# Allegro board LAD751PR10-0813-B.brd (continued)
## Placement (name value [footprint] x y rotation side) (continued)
PC512  0.022U_0402_25V7K  [C_0402]  133.09 140.24 180 bottom
PC513  0.01UF_0402_25V7K  [C_0402]  122.93 141.45 0 top
PC514  1500P_0402_50V7K  [C_0402]  134.03 143.89 270 bottom
PC515  0.01UF_0402_25V7K  [C_0402]  129.74 138.46 180 top
PC516  0.15U_0402_16V7K  [C_0402]  120.39 140.76 180 bottom
PC517  0.033U_0402_16V7K  [C_0402]  120.39 141.65 180 bottom
PC518  2200P_0402_50V7K  [C_0402]  121.39 143.63 270 bottom
PC519  330P_0402_50V7K  [C_0402]  129.68 143.21 90 top
PC520  68P_0402_50V8J  [C_0402]  127.89 142.34 0 top
PC521  2200P_0402_50V7K  [C_0402]  129.74 140.3 180 top
PC522  680P_0402_50V7K  [C_0402]  133.09 145.65 180 bottom
PC523  .1U_0402_16V7K  [C_0402]  120.49 145.4 0 bottom
PC524  0.022U_0402_25V7K  [C_0402]  130.03 146.02 90 bottom
PC525  0.022U_0402_25V7K  [C_0402]  120.68 142.99 0 top
PC526  0.022U_0402_25V7K  [C_0402]  128.19 145.96 90 top
PC527  0.022U_0402_25V7K  [C_0402]  127.3 145.96 90 top
PC528  0.022U_0402_25V7K  [C_0402]  120.68 142.1 0 top
PC529  .1U_0402_16V7K  [C_0402]  129.98 147.86 0 bottom
PC530  4700P_0402_16V7K  [C_0402]  125.27 146.94 270 top
PC531  0.22U_0402_16V7K  [C_0402]  126.15 146.94 270 top
PC532  2200P_0402_50V7K  [C_0402]  127.29 146.92 0 bottom
PC533  470P_0402_50V7K  [C_0402]  126.17 147.81 180 bottom
PC534  0.01UF_0402_25V7K  [C_0402]  127.13 144.64 270 top
PC535  330P_0402_50V7K  [C_0402]  123.87 142.85 90 top
PC536  68P_0402_50V8J  [C_0402]  125.04 142.54 270 top
PC537  680P_0402_50V7K  [C_0402]  123.5 147.81 180 bottom
PC538  6800P_0402_25V7K  [C_0402]  125.93 141.63 90 top
PC539  100U_25V_M  [C_ECST250ADA101MF611]  144.66 155 270 bottom
PC540  1U_0402_6.3V6K  [C_0402]  158.11 144.99 90 top
PC541  0.22U_0603_16V7K  [C_0603]  160.42 147.71 270 bottom
PC542  100U_25V_M  [C_ECST250ADA101MF611]  151.77 154.94 270 bottom
PC543  10U_0805_25V6K  [C_0805]  160.17 143.26 270 top
PC544  10U_0805_25V6K  [C_0805]  161.89 143.26 270 top
PC545  10U_0805_25V6K  [C_0805]  160.44 144.39 90 top
PC546  0.1U_0402_25V6  [C_0402]  163.19 141.8 0 top
PC547  2200P_0402_50V7K  [C_0402]  159.14 144.27 90 top
PC548  33P_0603_50V8J  [C_0603]  161.23 136.24 0 top
PC549  1U_0402_6.3V6K  [C_0402]  169.46 147.24 180 top
PC550  0.22U_0603_16V7K  [C_0603]  168.75 147.63 270 bottom
PC551  10U_0805_25V6K  [C_0805]  168.59 143.21 270 top
PC552  10U_0805_25V6K  [C_0805]  170.32 143.21 270 top
PC553  10U_0805_25V6K  [C_0805]  170.08 144.38 90 top
PC554  0.1U_0402_25V6  [C_0402]  171.4 144.22 90 top
PC555  2200P_0402_50V7K  [C_0402]  168.73 144.56 90 top
PC556  33P_0603_50V8J  [C_0603]  169.87 136.24 0 top
PC557  1U_0402_6.3V6K  [C_0402]  174.88 144.74 90 top
PC558  0.22U_0603_16V7K  [C_0603]  177.1 147.69 270 bottom
PC559  10U_0805_25V6K  [C_0805]  177.3 144.41 90 top
PC560  10U_0805_25V6K  [C_0805]  178.6 143.23 270 top
PC561  10U_0805_25V6K  [C_0805]  176.84 143.23 270 top
PC562  0.1U_0402_25V6  [C_0402]  178.65 144.25 90 top
PC563  2200P_0402_50V7K  [C_0402]  179.54 144.25 90 top
PC564  33P_0603_50V8J  [C_0603]  178.12 136.24 0 top
PC565  10U_0805_25V6K~D  [C_0805]  145.3 147.91 180 top
PC566  1U_0402_6.3V6K  [C_0402]  142.25 147.98 90 top
PC567  0.22U_0603_16V7K  [C_0603]  144.41 150.95 270 bottom
PC568  10U_0805_25V6K~D  [C_0805]  143.96 146.5 270 top
PC569  10U_0805_25V6K~D  [C_0805]  145.7 146.5 270 top
PC570  680P_0603_50V7K  [C_0603]  145.29 139.42 0 top
PC571  0.1U_0402_25V6  [C_0402]  147.15 147.49 90 top
PC572  2200P_0402_50V7K  [C_0402]  146.29 147.49 90 top
PC573  1U_0402_6.3V6K  [C_0402]  150.56 147.98 90 top
PC574  0.22U_0603_16V7K  [C_0603]  152.74 150.98 270 bottom
PC575  10U_0805_25V6K~D  [C_0805]  152.54 146.52 270 top
PC576  10U_0805_25V6K~D  [C_0805]  154.29 146.52 270 top
PC577  10U_0805_25V6K~D  [C_0805]  153.83 147.96 180 top
PC578  0.1U_0402_25V6  [C_0402]  154.83 147.52 90 top
PC579  2200P_0402_50V7K  [C_0402]  155.7 147.69 90 top
PC580  680P_0603_50V7K  [C_0603]  153.87 139.42 0 top
PC581  2200P_0402_50V7K  [C_0402]  186.89 139.4 270 top
PC582  0.1U_0402_25V6  [C_0402]  187.77 139.39 270 top
PC583  10U_0805_25V6K  [C_0805]  182.99 139.19 270 top
PC584  10U_0805_25V6K  [C_0805]  184.7 139.19 270 top
PC585  10U_0805_25V6K  [C_0805]  184.82 143.61 180 top
PC586  0.22U_0603_16V7K  [C_0603]  183.94 146.16 270 bottom
PC587  680P_0603_50V7K  [C_0603]  183.65 134.91 270 top
PC588  4.7U_0402_6.3V6M  [C_0402]  183.92 145.38 180 top
PC589  2200P_0402_50V7K  [C_0402]  118.64 117.38 180 bottom
PC590  0.22U_0402_10V6K  [C_0402]  124.58 117.7 0 bottom
PC591  680P_0603_50V7K  [C_0603]  118.44 108.11 270 bottom
PC592  10U_0805_25V6K  [C_0805]  120 119.73 0 bottom
PC593  0.1U_0603_25V7K  [C_0603]  119.45 113.13 0 bottom
PC594  0.1U_0402_25V6  [C_0402]  118.64 116.49 180 bottom
PC596  22U_0603_6.3V6M  [C_0603]  122.62 103.86 180 bottom
PC597  22U_0603_6.3V6M  [C_0603]  122.62 105.19 180 bottom
PC598  22U_0603_6.3V6M  [C_0603]  124.78 105.19 0 bottom
PC599  22U_0603_6.3V6M  [C_0603]  124.78 103.86 0 bottom
PC701  0.1U_0402_25V6  [C_0402]  58.05 28.67 180 top
PC702  0.047U_0402_25V7K  [C_0402]  61.78 23.21 0 top
PC703  0.1U_0402_25V6  [C_0402]  64.33 27.21 270 top
PC704  2200P_0402_50V7K  [C_0402]  63.45 27.21 270 top
PC705  10U_0805_25V6K~D  [C_0805]  65.73 27.08 270 top
PC706  10U_0805_25V6K~D  [C_0805]  67.51 27.08 270 top
PC707  0.1U_0603_25V7K  [C_0603]  58.37 22.61 90 bottom
PC708  0.1U_0402_25V6  [C_0402]  58.48 25.75 0 bottom
PC709  0.01UF_0402_25V7K  [C_0402]  59.64 24.56 270 bottom
PC710  2.2U_0603_16V6K  [C_0603]  59.23 21.37 180 bottom
PC711  1U_0603_25V6K  [C_0603]  59.44 22.64 0 bottom
PC712  22U_0805_25V6M  [C_0805]  82.47 26.91 90 bottom
PC713  22U_0805_25V6M  [C_0805]  84.18 26.91 90 bottom
PC714  22U_0805_25V6M  [C_0805]  86.03 26.94 90 bottom
PC715  680P_0402_50V7K  [C_0402]  63.76 21.04 90 top
PC716  0.1U_0402_25V6  [C_0402]  57.4 15.91 0 top
PC717  0.1U_0402_25V6  [C_0402]  58.31 16.8 180 top
PC718  100P_0402_50V8J  [C_0402]  52.96 24.69 0 top
PC719  0.01UF_0402_25V7K  [C_0402]  56.34 24.86 270 bottom
PC720  100P_0402_50V8J  [C_0402]  52.97 23.8 0 top
PC721  0.1U_0402_25V6  [C_0402]  56.52 16.81 270 top
PC722  1000P_0402_50V7K  [C_0402]  70.11 40.56 180 top
PC723  1000P_0402_50V7K  [C_0402]  69.92 33.37 180 top
PC724  0.1U_0402_25V6  [C_0402]  118.65 78.77 180 top
PC725  0.022U_0603_25V7K  [C_0603]  79.93 28.34 90 top
PC726  1000P_0402_50V7K  [C_0402]  62.56 27.22 270 top
PC727  1U_0402_25V6K  [C_0402]  61.67 27.22 270 top
PC800  10U_0805_25V6K~D  [C_0805]  245.12 38.77 90 bottom
PC801  0.1U_0402_16V7K  [C_0402]  238.08 39.85 180 bottom
PC802  680P_0402_50V7K  [C_0402]  247.8 45.31 0 bottom
PC803  2.2U_0402_16V6K  [C_0402]  241.31 42.78 270 top
PC804  22U_0603_6.3V6M  [C_0603]  240.42 46.58 90 bottom
PC805  22U_0603_6.3V6M  [C_0603]  239.15 46.58 90 bottom
PC806  680P_0402_50V7K  [C_0402]  234.44 44.04 0 bottom
PC807  2.2U_0402_16V6K  [C_0402]  122.61 113.44 0 bottom
PC808  0.1U_0603_25V7K  [C_0603]  248.62 42.95 180 bottom
PC809  330P_0402_50V7K  [C_0402]  237.17 43.4 0 bottom
PC810  10U_0805_25V6K~D  [C_0805]  229.93 35.4 0 bottom
PC811  0.1U_0402_16V7K  [C_0402]  226.07 38.56 90 bottom
PC812  22U_0603_6.3V6M  [C_0603]  224.86 44.81 270 bottom
PC813  22U_0603_6.3V6M  [C_0603]  223.59 44.81 270 bottom
PC814  10U_0805_25V6K~D  [C_0805]  229.85 37.12 0 bottom
PC815  22U_0603_6.3V6M  [C_0603]  236.67 46.58 90 bottom
PC816  22U_0603_6.3V6M  [C_0603]  237.94 46.58 90 bottom
PC817  1U_0603_6.3V6M  [C_0603]  239.14 44.3 0 bottom
PC818  330P_0402_50V7K  [C_0402]  122.13 122.84 180 bottom
PC819  330P_0402_50V7K  [C_0402]  222.45 42.53 270 bottom
PC820  22U_0603_6.3V6M  [C_0603]  224.86 45.78 90 bottom
PC821  1U_0603_6.3V6M  [C_0603]  226.13 42.32 180 bottom
PC822  2.2U_0402_16V6K  [C_0402]  229.56 43.4 180 bottom
PC823  0.1U_0603_25V7K  [C_0603]  234.07 42.45 180 bottom
PC824  22U_0603_6.3V6M  [C_0603]  223.59 45.78 90 bottom
PC1000  220U_D7_2VM_R6M  [C_EEFSS0D221R]  164.07 125.32 0 bottom
PC1001  220U 2.5V Y D2 ESR9M H1.9 SX  [C_D2]  170.89 125.35 0 top
PC1002  220U 2.5V Y D2 ESR9M H1.9 SX  [C_D2]  161.7 125.38 180 top
PC1003  47U_0603_6.3V6M  [C_0603]  177.04 126.68 270 bottom
PC1004  47U_0603_6.3V6M  [C_0603]  175.14 126.68 270 bottom
PC1005  47U_0805_6.3V6M  [C_0805]  164.77 107.09 0 top
PC1006  47U_0603_6.3V6M  [C_0603]  178.95 126.68 270 bottom
PC1007  220U 2.5V Y D2 ESR9M H1.9 SX  [C_D2]  151.8 130.33 180 top
PC1008  220U_D7_2VM_R6M  [C_EEFSS0D221R]  149.51 126.21 180 bottom
PC1009  220U_D7_2VM_R6M  [C_EEFSS0D221R]  151.67 125.51 180 top
PC1010  220U_D7_2VM_R6M  [C_EEFSS0D221R]  153.78 126.27 0 bottom
PC1011  47U_0603_6.3V6M  [C_0603]  153.03 131.85 0 bottom
PC1012  47U_0603_6.3V6M  [C_0603]  144.85 131.86 0 bottom
PC1013  47U_0603_6.3V6M  [C_0603]  153.03 130.61 0 bottom
PC1014  47U_0603_6.3V6M  [C_0603]  144.85 130.65 0 bottom
PC1015  47U_0603_6.3V6M  [C_0603]  153.03 129.34 0 bottom
PC1016  47U_0603_6.3V6M  [C_0603]  144.85 129.38 0 bottom
PC1017  220U_D2_2.5VY_R9M  [C_D2]  180.83 125.38 0 top
PC1018  47U_0805_6.3V6M  [C_0805]  164.77 108.8 0 top
PC1019  10U_0402_6.3V6M  [C_0402]  165.55 113.06 0 top
PC1020  22U_0603_6.3V6M  [C_0603]  156.86 107.66 0 top
PC1021  22U_0603_6.3V6M  [C_0603]  156.86 106.46 0 top
PC1022  22U_0603_6.3V6M  [C_0603]  155.91 107.66 180 top
PC1023  22U_0603_6.3V6M  [C_0603]  155.91 106.46 180 top
PC1024  22U_0603_6.3V6M  [C_0603]  160.61 106.46 180 top
PC1025  22U_0603_6.3V6M  [C_0603]  160.61 107.66 180 top
PC1026  22U_0603_6.3V6M  [C_0603]  161.56 107.66 0 top
PC1027  22U_0603_6.3V6M  [C_0603]  161.56 106.46 0 top
PC1028  22U_0603_6.3V6M  [C_0603]  140.73 108.04 0 top
PC1029  22U_0603_6.3V6M  [C_0603]  138.38 108.04 0 top
PC1030  22U_0603_6.3V6M  [C_0603]  145.43 108.04 0 top
PC1031  22U_0603_6.3V6M  [C_0603]  143.08 108.04 0 top
PC1032  22U_0603_6.3V6M  [C_0603]  147.78 108.04 0 top
PC1033  22U_0603_6.3V6M  [C_0603]  150.51 108.11 0 top
PC1034  22U_0603_6.3V6M  [C_0603]  150.52 109.32 0 top
PC1035  22U_0603_6.3V6M  [C_0603]  150.52 110.66 0 top
PC1036  10U_0402_6.3V6M  [C_0402]  164.68 111.03 180 top
PC1037  10U_0402_6.3V6M  [C_0402]  165.55 112.17 0 top
PC1038  10U_0402_6.3V6M  [C_0402]  165.55 114.46 0 top
PC1039  10U_0402_6.3V6M  [C_0402]  164.68 111.92 180 top
PC1040  10U_0402_6.3V6M  [C_0402]  164.68 110.14 180 top
PC1041  10U_0402_6.3V6M  [C_0402]  165.55 110.14 0 top
PC1042  1U_0201_6.3V6M  [C_0201]  164.84 113.69 180 top
PC1043  1U_0201_6.3V6M  [C_0201]  164.84 114.84 180 top
PC1044  1U_0201_6.3V6M  [C_0201]  164.84 114.27 180 top
PC1045  10U_0402_6.3V6M  [C_0402]  155.48 111.03 180 top
PC1046  10U_0402_6.3V6M  [C_0402]  156.34 109.76 0 top
PC1047  10U_0402_6.3V6M  [C_0402]  155.48 111.92 180 top
PC1048  10U_0402_6.3V6M  [C_0402]  155.48 109.76 180 top
PC1049  10U_0402_6.3V6M  [C_0402]  156.34 111.92 0 top
PC1050  10U_0402_6.3V6M  [C_0402]  158.91 105.19 180 top
PC1051  10U_0402_6.3V6M  [C_0402]  156.34 111.03 0 top
PC1052  10U_0402_6.3V6M  [C_0402]  156.21 105.19 0 top
PC1053  10U_0402_6.3V6M  [C_0402]  158.91 104.3 180 top
PC1054  10U_0402_6.3V6M  [C_0402]  160.09 109.76 0 top
PC1055  10U_0402_6.3V6M  [C_0402]  156.21 104.3 0 top
PC1056  10U_0402_6.3V6M  [C_0402]  159.22 109.76 180 top
PC1057  10U_0402_6.3V6M  [C_0402]  159.22 111.92 180 top
PC1058  10U_0402_6.3V6M  [C_0402]  159.22 111.03 180 top
PC1059  10U_0402_6.3V6M  [C_0402]  153.08 112.72 180 top
PC1060  10U_0402_6.3V6M  [C_0402]  143.12 105.72 0 top
PC1061  10U_0402_6.3V6M  [C_0402]  138.56 104.8 0 top
PC1062  10U_0402_6.3V6M  [C_0402]  140.84 106.6 0 top
PC1063  10U_0402_6.3V6M  [C_0402]  140.85 111.39 0 top
PC1064  10U_0402_6.3V6M  [C_0402]  148.03 109.12 0 top
PC1065  10U_0402_6.3V6M  [C_0402]  145.56 109.11 0 top
PC1066  10U_0402_6.3V6M  [C_0402]  138.6 110.48 0 top
PC1067  10U_0402_6.3V6M  [C_0402]  143.14 111.39 0 top
PC1068  10U_0402_6.3V6M  [C_0402]  138.56 105.7 0 top
PC1069  10U_0402_6.3V6M  [C_0402]  143.12 104.81 0 top
PC1070  10U_0402_6.3V6M  [C_0402]  140.86 110.52 0 top
PC1071  10U_0402_6.3V6M  [C_0402]  160.09 111.92 0 top
PC1072  10U_0402_6.3V6M  [C_0402]  159.77 104.3 0 top
PC1073  10U_0402_6.3V6M  [C_0402]  160.09 111.03 0 top
PC1074  10U_0402_6.3V6M  [C_0402]  159.77 105.19 0 top
PC1075  10U_0402_6.3V6M  [C_0402]  162.78 111.92 180 top
PC1076  10U_0402_6.3V6M  [C_0402]  162.78 109.76 180 top
PC1077  10U_0402_6.3V6M  [C_0402]  162.46 104.3 180 top
PC1078  10U_0402_6.3V6M  [C_0402]  162.78 111.03 180 top
PC1079  10U_0402_6.3V6M  [C_0402]  163.33 104.3 0 top
PC1080  10U_0402_6.3V6M  [C_0402]  163.33 105.19 0 top
PC1081  10U_0402_6.3V6M  [C_0402]  166.02 105.19 180 top
PC1082  10U_0402_6.3V6M  [C_0402]  162.46 105.19 180 top
PC1083  10U_0402_6.3V6M  [C_0402]  155.35 105.19 180 top
PC1084  10U_0402_6.3V6M  [C_0402]  155.35 104.3 180 top
PC1085  10U_0402_6.3V6M  [C_0402]  147.78 104.79 0 top
PC1086  10U_0402_6.3V6M  [C_0402]  147.79 106.59 0 top
PC1087  10U_0402_6.3V6M  [C_0402]  145.45 104.79 0 top
PC1088  10U_0402_6.3V6M  [C_0402]  147.97 111.44 0 top
PC1089  10U_0402_6.3V6M  [C_0402]  145.44 106.59 0 top
PC1090  10U_0402_6.3V6M  [C_0402]  150.05 104.8 0 top
PC1091  10U_0402_6.3V6M  [C_0402]  153.05 111.85 180 top
PC1092  10U_0402_6.3V6M  [C_0402]  145.44 105.69 0 top
PC1093  10U_0402_6.3V6M  [C_0402]  150.06 105.68 0 top
PC1094  10U_0402_6.3V6M  [C_0402]  140.83 104.81 0 top
PC1095  10U_0402_6.3V6M  [C_0402]  145.49 111.4 0 top
PC1096  10U_0402_6.3V6M  [C_0402]  143.14 110.52 0 top
PC1097  1U_0201_6.3V6M  [C_0201]  163.12 101.12 180 top
PC1098  1U_0201_6.3V6M  [C_0201]  164.65 102.58 180 top
PC1099  1U_0201_6.3V6M  [C_0201]  165.68 124.94 270 top
PC1100  1U_0201_6.3V6M  [C_0201]  159.82 109 180 top
PC1101  1U_0201_6.3V6M  [C_0201]  165.27 102.58 0 top
PC1102  1U_0201_6.3V6M  [C_0201]  162.6 113.25 0 top
PC1103  1U_0201_6.3V6M  [C_0201]  162.6 112.68 0 top
PC1104  1U_0201_6.3V6M  [C_0201]  161.98 113.25 180 top
PC1105  1U_0201_6.3V6M  [C_0201]  162.23 109 180 top
PC1106  1U_0201_6.3V6M  [C_0201]  161.98 112.68 180 top
PC1107  1U_0201_6.3V6M  [C_0201]  161.98 114.27 180 top
PC1108  1U_0201_6.3V6M  [C_0201]  161.98 114.84 180 top
PC1109  1U_0201_6.3V6M  [C_0201]  162.6 114.84 0 top
PC1110  1U_0201_6.3V6M  [C_0201]  162.6 114.27 0 top
PC1111  1U_0201_6.3V6M  [C_0201]  160.44 109 0 top
PC1112  10U_0402_6.3V6M  [C_0402]  145.51 110.52 0 top
PC1113  10U_0402_6.3V6M  [C_0402]  150.08 106.58 0 top
PC1114  10U_0402_6.3V6M  [C_0402]  138.56 106.6 0 top
PC1115  10U_0402_6.3V6M  [C_0402]  140.88 109.12 0 top
PC1116  10U_0402_6.3V6M  [C_0402]  140.84 105.7 0 top
PC1117  10U_0402_6.3V6M  [C_0402]  138.6 111.37 0 top
PC1118  10U_0402_6.3V6M  [C_0402]  138.58 109.13 0 top
PC1119  10U_0402_6.3V6M  [C_0402]  147.98 110.53 0 top
PC1120  10U_0402_6.3V6M  [C_0402]  143.12 106.62 0 top
PC1121  10U_0402_6.3V6M  [C_0402]  147.79 105.69 0 top
PC1122  10U_0402_6.3V6M  [C_0402]  143.12 109.11 0 top
PC1123  1U_0201_6.3V6M  [C_0201]  155.36 113.25 0 top
PC1124  1U_0201_6.3V6M  [C_0201]  157.15 112.68 180 top
PC1125  1U_0201_6.3V6M  [C_0201]  155.36 112.68 0 top
PC1126  1U_0201_6.3V6M  [C_0201]  154.74 113.25 180 top
PC1127  1U_0201_6.3V6M  [C_0201]  157.15 113.25 180 top
PC1128  1U_0201_6.3V6M  [C_0201]  157.15 114.84 180 top
PC1129  1U_0201_6.3V6M  [C_0201]  154.74 112.68 180 top
PC1130  1U_0201_6.3V6M  [C_0201]  157.15 114.27 180 top
PC1131  1U_0201_6.3V6M  [C_0201]  155.36 114.84 0 top
PC1132  1U_0201_6.3V6M  [C_0201]  155.36 114.27 0 top
PC1133  1U_0201_6.3V6M  [C_0201]  154.74 114.27 180 top
PC1134  1U_0201_6.3V6M  [C_0201]  163.74 101.12 0 top
PC1135  1U_0201_6.3V6M  [C_0201]  154.74 114.84 180 top
PC1136  1U_0201_6.3V6M  [C_0201]  162.86 109 0 top
PC1137  1U_0201_6.3V6M  [C_0201]  160.44 103.15 0 top
PC1138  1U_0201_6.3V6M  [C_0201]  152.57 113.9 180 top
PC1139  1U_0201_6.3V6M  [C_0201]  145.87 114.44 0 top
PC1140  1U_0201_6.3V6M  [C_0201]  144.03 103.5 180 top
PC1141  1U_0201_6.3V6M  [C_0201]  150.13 113.89 180 top
PC1142  1U_0201_6.3V6M  [C_0201]  150.18 112.26 180 top
PC1143  1U_0201_6.3V6M  [C_0201]  146.68 103.51 180 top
PC1144  1U_0201_6.3V6M  [C_0201]  149.09 102.94 180 top
PC1145  1U_0201_6.3V6M  [C_0201]  138.49 112.78 0 top
PC1146  1U_0201_6.3V6M  [C_0201]  149.09 103.51 180 top
PC1147  1U_0201_6.3V6M  [C_0201]  144.03 102.92 180 top
PC1148  1U_0201_6.3V6M  [C_0201]  149.71 102.94 0 top
PC1149  1U_0201_6.3V6M  [C_0201]  140.31 112.19 180 top
PC1150  1U_0201_6.3V6M  [C_0201]  150.18 112.85 180 top
PC1151  1U_0201_6.3V6M  [C_0201]  140.96 112.78 0 top
PC1152  1U_0201_6.3V6M  [C_0201]  148.38 112.26 0 top
PC1153  1U_0201_6.3V6M  [C_0201]  142.79 112.19 180 top
PC1154  1U_0201_6.3V6M  [C_0201]  148.38 112.84 0 top
PC1155  1U_0201_6.3V6M  [C_0201]  143.45 112.79 0 top
PC1156  1U_0201_6.3V6M  [C_0201]  149.71 103.51 0 top
PC1157  1U_0201_6.3V6M  [C_0201]  148.33 113.88 0 top
PC1158  1U_0201_6.3V6M  [C_0201]  150.81 112.28 0 top
PC1159  1U_0201_6.3V6M  [C_0201]  148.33 114.46 0 top
PC1160  1U_0201_6.3V6M  [C_0201]  152.57 114.47 180 top
PC1161  1U_0201_6.3V6M  [C_0201]  166.25 124.94 270 top
PC1162  1U_0201_6.3V6M  [C_0201]  164.41 123.35 0 top
PC1163  1U_0201_6.3V6M  [C_0201]  162.23 103.15 180 top
PC1164  1U_0201_6.3V6M  [C_0201]  162.86 103.15 0 top
PC1165  1U_0201_6.3V6M  [C_0201]  158.03 103.15 0 top
PC1166  1U_0201_6.3V6M  [C_0201]  158.03 109 0 top
PC1167  1U_0201_6.3V6M  [C_0201]  159.82 103.15 180 top
PC1168  1U_0201_6.3V6M  [C_0201]  159.57 112.68 180 top
PC1169  1U_0201_6.3V6M  [C_0201]  157.41 109 180 top
PC1170  1U_0201_6.3V6M  [C_0201]  160.19 113.25 0 top
PC1171  1U_0201_6.3V6M  [C_0201]  159.57 113.25 180 top
PC1172  1U_0201_6.3V6M  [C_0201]  160.19 112.68 0 top
PC1173  1U_0201_6.3V6M  [C_0201]  157.78 112.68 0 top
PC1174  1U_0201_6.3V6M  [C_0201]  157.78 113.25 0 top
PC1175  1U_0201_6.3V6M  [C_0201]  159.57 114.27 180 top
PC1176  1U_0201_6.3V6M  [C_0201]  144.88 103.51 0 top
PC1177  1U_0201_6.3V6M  [C_0201]  145.9 112.23 0 top
PC1178  1U_0201_6.3V6M  [C_0201]  144.88 102.94 0 top
PC1179  1U_0201_6.3V6M  [C_0201]  145.87 113.86 0 top
PC1180  1U_0201_6.3V6M  [C_0201]  142.77 113.84 180 top
PC1181  1U_0201_6.3V6M  [C_0201]  147.3 103.51 0 top
PC1182  1U_0201_6.3V6M  [C_0201]  146.68 102.94 180 top
PC1183  1U_0201_6.3V6M  [C_0201]  145.23 114.43 180 top
PC1184  1U_0201_6.3V6M  [C_0201]  145.27 112.8 180 top
PC1185  1U_0201_6.3V6M  [C_0201]  145.23 113.85 180 top
PC1186  1U_0201_6.3V6M  [C_0201]  139.82 102.92 0 top
PC1187  1U_0201_6.3V6M  [C_0201]  138.48 112.19 0 top
PC1188  1U_0201_6.3V6M  [C_0201]  140.31 112.77 180 top
PC1189  1U_0201_6.3V6M  [C_0201]  139.2 103.49 180 top
PC1190  1U_0201_6.3V6M  [C_0201]  140.3 114.42 180 top
PC1191  1U_0201_6.3V6M  [C_0201]  139.2 102.92 180 top
PC1192  1U_0201_6.3V6M  [C_0201]  140.3 113.84 180 top
PC1193  1U_0201_6.3V6M  [C_0201]  145.27 112.21 180 top
PC1194  1U_0201_6.3V6M  [C_0201]  150.13 114.47 180 top
PC1195  1U_0201_6.3V6M  [C_0201]  143.42 113.86 0 top
PC1196  1U_0201_6.3V6M  [C_0201]  140.96 112.19 0 top
PC1197  1U_0201_6.3V6M  [C_0201]  143.41 114.43 0 top
PC1198  1U_0201_6.3V6M  [C_0201]  147.3 102.94 0 top
PC1199  1U_0201_6.3V6M  [C_0201]  159.57 114.84 180 top
PC1200  1U_0201_6.3V6M  [C_0201]  157.78 114.27 0 top
PC1201  1U_0201_6.3V6M  [C_0201]  157.78 114.84 0 top
PC1202  1U_0201_6.3V6M  [C_0201]  160.19 114.27 0 top
PC1203  1U_0201_6.3V6M  [C_0201]  160.19 114.84 0 top
PC1204  1U_0201_6.3V6M  [C_0201]  165.27 103.15 0 top
PC1205  1U_0201_6.3V6M  [C_0201]  164.65 103.15 180 top
PC1206  1U_0201_6.3V6M  [C_0201]  154.99 102.58 180 top
PC1207  1U_0201_6.3V6M  [C_0201]  164.41 123.92 0 top
PC1208  1U_0201_6.3V6M  [C_0201]  154.99 103.15 180 top
PC1209  1U_0201_6.3V6M  [C_0201]  155.62 103.15 0 top
PC1210  1U_0201_6.3V6M  [C_0201]  155.44 101.76 180 top
PC1211  1U_0201_6.3V6M  [C_0201]  155.62 102.58 0 top
PC1212  1U_0201_6.3V6M  [C_0201]  157.41 102.58 180 top
PC1213  1U_0201_6.3V6M  [C_0201]  157.85 101.12 180 top
PC1214  1U_0201_6.3V6M  [C_0201]  145.9 112.81 0 top
PC1215  1U_0201_6.3V6M  [C_0201]  142.79 112.78 180 top
PC1216  1U_0201_6.3V6M  [C_0201]  150.81 112.87 0 top
PC1217  1U_0201_6.3V6M  [C_0201]  147.69 114.45 180 top
PC1218  1U_0201_6.3V6M  [C_0201]  150.77 113.89 0 top
PC1219  1U_0201_6.3V6M  [C_0201]  140.95 114.42 0 top
PC1220  1U_0201_6.3V6M  [C_0201]  151.5 102.94 180 top
PC1221  1U_0201_6.3V6M  [C_0201]  143.44 112.2 0 top
PC1222  1U_0201_6.3V6M  [C_0201]  142.77 114.42 180 top
PC1223  1U_0201_6.3V6M  [C_0201]  142.24 103.49 0 top
PC1224  1U_0201_6.3V6M  [C_0201]  140.95 113.82 0 top
PC1225  1U_0201_6.3V6M  [C_0201]  138.48 113.84 0 top
PC1226  1U_0201_6.3V6M  [C_0201]  138.47 114.43 0 top
PC1227  1U_0201_6.3V6M  [C_0201]  139.82 103.49 0 top
PC1228  1U_0201_6.3V6M  [C_0201]  150.77 114.46 0 top
PC1229  1U_0201_6.3V6M  [C_0201]  141.62 102.93 180 top
PC1230  1U_0201_6.3V6M  [C_0201]  147.74 112.25 180 top
PC1231  1U_0201_6.3V6M  [C_0201]  142.25 102.91 0 top
PC1232  1U_0201_6.3V6M  [C_0201]  147.69 113.86 180 top
PC1233  1U_0201_6.3V6M  [C_0201]  151.5 103.51 180 top
PC1234  1U_0201_6.3V6M  [C_0201]  147.74 112.83 180 top
PC1235  1U_0201_6.3V6M  [C_0201]  141.62 103.5 180 top
PC1236  1U_0201_6.3V6M  [C_0201]  155.62 109 0 top
PC1237  1U_0201_6.3V6M  [C_0201]  157.41 103.15 180 top
PC1238  1U_0201_6.3V6M  [C_0201]  154.99 109 180 top
PC1300  22U_0603_6.3V6M  [C_0603]  101.71 51.96 0 bottom
PC1301  0.1U_0402_16V7K  [C_0402]  100.12 50.71 90 bottom
PC1303  22U_0603_6.3V6M  [C_0603]  101.1 38.64 180 bottom
PC1304  22U_0603_6.3V6M  [C_0603]  101.1 39.85 180 bottom
PC1305  22P_0603_50V8  [C_0603]  101.1 41.05 180 bottom
PC1306  22U_0603_6.3V6M  [C_0603]  101.71 50.75 0 bottom
PC1307  1U_0603_6.3V6M  [C_0603]  104.18 49.63 270 bottom
PC5002  4.7U_0402_6.3V6M  [C_0402]  181.87 140.67 90 top
PC5003  1U_0603_6.3V6M  [C_0603]  124.53 113.63 0 bottom
PC5005  1U_0402_6.3V6K  [C_0402]  157.33 141.51 270 top
PC5006  1U_0402_6.3V6K  [C_0402]  165.88 140.13 0 top
PC5007  1U_0402_6.3V6K  [C_0402]  174.03 141.54 270 top
PC5008  1U_0402_6.3V6K  [C_0402]  141.33 144.79 270 top
PC5009  1U_0402_6.3V6K  [C_0402]  149.63 144.85 270 top
PC5010  1000P_0402_50V7K  [C_0402]  119.56 134.34 0 bottom
PC5011  1000P_0402_50V7K  [C_0402]  120.5 147.19 270 bottom
PC5013  1U_0402_25V6K  [C_0402]  163.2 142.69 0 top
PC5014  1000P_0402_50V7K  [C_0402]  163.19 140.93 0 top
PC5015  1U_0402_25V6K  [C_0402]  171.59 142.55 0 top
PC5016  1000P_0402_50V7K  [C_0402]  172.6 145.13 90 top
PC5017  1U_0402_25V6K  [C_0402]  179.91 142.81 270 top
PC5018  1000P_0402_50V7K  [C_0402]  180.87 145.26 90 top
PC5019  1U_0402_25V6K  [C_0402]  147.14 145.89 0 top
PC5020  1000P_0402_50V7K  [C_0402]  148.25 148.49 90 top
PC5021  1U_0402_25V6K  [C_0402]  155.61 145.96 270 top
PC5022  1000P_0402_50V7K  [C_0402]  156.56 148.08 90 top
PC5023  1U_0402_25V6K  [C_0402]  184.98 142.17 180 top
PC5024  1000P_0402_50V7K  [C_0402]  186.01 139.42 270 top
PC5025  1U_0402_25V6K  [C_0402]  118.64 119.22 180 bottom
PC5026  1000P_0402_50V7K  [C_0402]  118.63 118.3 180 bottom
PC6000  0.1U_0402_25V6  [C_0402]  267.29 143.3 180 bottom
PC6001  0.1U_0402_25V6  [C_0402]  270.68 137.64 180 bottom
PC6002  0.01U_0402_16V7K  [C_0402]  267.29 140.62 180 bottom
PC6003  0.1U_0402_25V6  [C_0402]  266.9 132.06 270 bottom
PC6004  0.1U_0402_25V6  [C_0402]  266.9 133.97 270 bottom
PC6005  0.015U_0402_16V7K  [C_0402]  268.88 142.08 270 bottom
PC6006  0.12U_0402_10V6K  [C_0402]  266.9 137.71 270 bottom
PC6007  0.1U_0402_25V6  [C_0402]  269.74 142.08 0 bottom
PC6008  0.1U_0402_10V6K  [C_0402]  269.73 134.94 0 bottom
PC6009  0.1U_0402_25V6  [C_0402]  272.42 144.82 270 bottom
PC6010  0.1U_0402_25V6  [C_0402]  273.31 143.91 90 bottom
PC6011  0.1U_0402_25V6  [C_0402]  270.65 144.82 270 bottom
PC6012  0.1U_0402_25V6  [C_0402]  274.2 144.82 270 bottom
PC6014  1U_0402_6.3V6K  [C_0402]  276.23 135.78 90 top
PC6015  4700P_0402_50V7K  [C_0402]  281.81 140.05 0 bottom
PC6016  0.01U_0402_16V  [C_0402]  277.49 139.29 0 top
PC6017  0.1U_0402_25V6  [C_0402]  270.66 139.41 180 bottom
PC6100  1U_0402_25V6K  [C_0402]  260.68 150.32 90 bottom
PC6101  1U_0603_16V7  [C_0603]  254.92 151.44 270 top
PC6102  0.1U_0603_50V7K  [C_0603]  256.17 154.27 270 top
PC6103  1U_0603_16V7  [C_0603]  250.71 149.19 270 top
PC6104  1000P_0402_50V7K  [C_0402]  261.57 150.32 90 bottom
PC6105  0.1U_0402_25V6  [C_0402]  262.48 150.32 90 bottom
PC6106  2200P_0402_50V7K  [C_0402]  263.36 150.32 90 bottom
PC6107  10U_0805_25V6K~D  [C_0805]  261.06 148.65 270 bottom
PC6108  470U_D2_2VM_R4.5M~D  [C_D1]  234.46 133.76 180 top
PC6109  10U_0805_25V6K~D  [C_0805]  259.28 148.65 270 bottom
PC6110  10U_0805_25V6K~D  [C_0805]  259.28 150.5 90 bottom
PC6111  10U_0805_25V6K~D  [C_0805]  262.9 148.65 270 bottom
PC6112  33U_D2_25VM_R40M  [C_EEFCX1E330R]  261.57 151.78 90 top
PC6113  3300P_0805_50V7K  [C_0805]  259.76 143.06 0 top
PC6114  1U_0603_16V7  [C_0603]  241.03 151.4 270 top
PC6115  0.1U_0603_50V7K  [C_0603]  242.32 154.27 270 top
PC6116  1U_0603_16V7  [C_0603]  236.93 149.13 270 top
PC6117  1U_0402_25V6K  [C_0402]  246.9 150.26 90 bottom
PC6118  1000P_0402_50V7K  [C_0402]  247.79 150.26 90 bottom
PC6119  0.1U_0402_25V6  [C_0402]  248.7 150.26 90 bottom
PC6120  2200P_0402_50V7K  [C_0402]  249.58 150.26 90 bottom
PC6121  10U_0805_25V6K~D  [C_0805]  245.5 148.58 270 bottom
PC6122  10U_0805_25V6K~D  [C_0805]  247.28 148.58 270 bottom
PC6123  33U_D2_25VM_R40M  [C_EEFCX1E330R]  247.72 151.72 90 top
PC6124  470U_D2_2VM_R4.5M~D  [C_D1]  225.45 133.7 180 top
PC6125  10U_0805_25V6K~D  [C_0805]  249.12 148.58 270 bottom
PC6126  10U_0805_25V6K~D  [C_0805]  245.5 150.44 90 bottom
PC6127  3300P_0805_50V7K  [C_0805]  245.98 143 0 top
PC6200  1U_0402_25V6K  [C_0402]  233.18 150.2 90 bottom
PC6201  1U_0603_16V7  [C_0603]  227.24 151.43 270 top
PC6202  0.1U_0603_50V7K  [C_0603]  228.67 154.15 270 top
PC6203  1U_0603_16V7  [C_0603]  223.47 147.48 270 bottom
PC6204  1000P_0402_50V7K  [C_0402]  234.07 150.2 90 bottom
PC6205  0.1U_0402_25V6  [C_0402]  234.98 150.2 90 bottom
PC6206  2200P_0402_50V7K  [C_0402]  235.86 150.2 90 bottom
PC6207  470U_D2_2VM_R4.5M~D  [C_D1]  245.81 122.14 0 bottom
PC6208  10U_0805_25V6K~D  [C_0805]  231.78 150.37 90 bottom
PC6209  10U_0805_25V6K~D  [C_0805]  235.4 148.52 270 bottom
PC6210  10U_0805_25V6K~D  [C_0805]  233.56 148.52 270 bottom
PC6211  10U_0805_25V6K~D  [C_0805]  231.78 148.52 270 bottom
PC6212  33U_D2_25VM_R40M  [C_EEFCX1E330R]  233.94 151.66 90 top
PC6213  3300P_0805_50V7K  [C_0805]  232.2 142.87 0 top
PC6214  1U_0603_16V7  [C_0603]  212.73 153 90 bottom
PC6215  0.1U_0603_50V7K  [C_0603]  214.89 154.11 270 bottom
PC6216  1U_0603_16V7  [C_0603]  209.62 148.18 270 bottom
PC6217  1U_0402_25V6K  [C_0402]  221.05 150.39 90 top
PC6218  1000P_0402_50V7K  [C_0402]  220.16 150.39 90 top
PC6219  0.1U_0402_25V6  [C_0402]  219.25 150.39 90 top
PC6220  2200P_0402_50V7K  [C_0402]  221.94 150.39 90 top
PC6221  470U_D2_2VM_R4.5M~D  [C_D1]  243.61 133.76 180 top
PC6222  10U_0805_25V6K~D  [C_0805]  216.35 152.79 90 bottom
PC6223  10U_0805_25V6K~D  [C_0805]  221.75 148.46 270 bottom
PC6224  10U_0805_25V6K~D  [C_0805]  219.91 148.46 270 bottom
PC6225  10U_0805_25V6K~D  [C_0805]  218.13 148.46 270 bottom
PC6226  33U_D2_25VM_R40M  [C_EEFCX1E330R]  219.72 150.93 270 bottom
PC6227  3300P_0805_50V7K  [C_0805]  207.23 142.15 0 bottom
PC6300  1U_0402_6.3V6K  [C_0402]  245.83 95.04 270 top
PC6301  1U_0402_6.3V6K  [C_0402]  242.41 96.03 270 top
PC6302  1U_0402_6.3V6K  [C_0402]  242.45 89.64 270 top
PC6303  1U_0402_6.3V6K  [C_0402]  227.67 104.54 90 top
PC6304  1U_0402_6.3V6K  [C_0402]  246.01 100.79 90 top
PC6305  1U_0402_6.3V6K  [C_0402]  231.23 105.26 270 top
PC6306  1U_0402_6.3V6K  [C_0402]  231.23 103.47 270 top
PC6307  1U_0402_6.3V6K  [C_0402]  231.23 100.79 90 top
PC6308  1U_0402_6.3V6K  [C_0402]  232.63 106.13 90 top
PC6309  1U_0402_6.3V6K  [C_0402]  234.02 106.13 90 top
PC6310  1U_0402_6.3V6K  [C_0402]  232.63 105.26 270 top
PC6311  1U_0402_6.3V6K  [C_0402]  234.02 105.26 270 top
PC6312  1U_0402_6.3V6K  [C_0402]  239.61 94.28 270 top
PC6313  1U_0402_6.3V6K  [C_0402]  239.61 96.03 270 top
PC6314  1U_0402_6.3V6K  [C_0402]  243.8 90.89 90 top
PC6315  1U_0402_6.3V6K  [C_0402]  243.8 96.49 270 top
PC6316  1U_0402_6.3V6K  [C_0402]  243.8 100.81 270 top
PC6317  1U_0402_6.3V6K  [C_0402]  244.63 105.75 180 top
PC6318  1U_0402_6.3V6K  [C_0402]  229.83 106.14 90 top
PC6319  1U_0402_6.3V6K  [C_0402]  229.83 99.09 90 top
PC6320  1U_0402_6.3V6K  [C_0402]  229.83 98.22 270 top
PC6321  1U_0402_6.3V6K  [C_0402]  243.8 103.98 90 top
PC6322  1U_0402_6.3V6K  [C_0402]  240.94 92.5 270 top
PC6323  1U_0402_6.3V6K  [C_0402]  253.06 118.07 90 top
PC6324  1U_0402_6.3V6K  [C_0402]  227.78 100.48 90 top
PC6325  1U_0402_6.3V6K  [C_0402]  240.94 97.78 270 top
PC6326  1U_0402_6.3V6K  [C_0402]  239.61 97.78 270 top
PC6327  1U_0402_6.3V6K  [C_0402]  252.23 112.3 0 top
PC6328  1U_0402_6.3V6K  [C_0402]  246.01 96.48 90 top
PC6329  1U_0402_6.3V6K  [C_0402]  245.82 103.49 270 top
PC6330  1U_0402_6.3V6K  [C_0402]  231.23 106.13 90 top
PC6331  1U_0402_6.3V6K  [C_0402]  227.74 98.25 90 top
PC6332  1U_0402_6.3V6K  [C_0402]  252.23 113.32 0 top
PC6333  1U_0402_6.3V6K  [C_0402]  240.94 96.03 270 top
PC6334  1U_0402_6.3V6K  [C_0402]  239.61 92.49 270 top
PC6335  1U_0402_6.3V6K  [C_0402]  254.33 115.4 90 top
PC6336  1U_0402_6.3V6K  [C_0402]  229.83 100.93 90 top
PC6337  1U_0402_6.3V6K  [C_0402]  243.8 93.82 270 top
PC6338  1U_0402_6.3V6K  [C_0402]  243.8 98.34 270 top
PC6339  1U_0402_6.3V6K  [C_0402]  243.8 103.17 270 top
PC6340  1U_0402_6.3V6K  [C_0402]  229.83 103.85 270 top
PC6341  1U_0402_6.3V6K  [C_0402]  229.83 93.57 90 top
PC6342  1U_0402_6.3V6K  [C_0402]  229.77 90.82 90 top
PC6343  1U_0402_6.3V6K  [C_0402]  229.83 96.46 270 top
PC6344  1U_0402_6.3V6K  [C_0402]  252.23 111.28 0 top
PC6345  1U_0402_6.3V6K  [C_0402]  227.8 95.22 270 top
PC6346  1U_0402_6.3V6K  [C_0402]  242.34 92.5 270 top
PC6347  1U_0402_6.3V6K  [C_0402]  245.9 105.51 270 top
PC6348  1U_0402_6.3V6K  [C_0402]  232.63 100.79 90 top
PC6349  1U_0402_6.3V6K  [C_0402]  232.63 103.47 270 top
PC6350  1U_0402_6.3V6K  [C_0402]  233.27 88.74 180 top
PC6351  1U_0402_6.3V6K  [C_0402]  234.02 100.79 90 top
PC6352  1U_0402_6.3V6K  [C_0402]  255.79 106.79 270 top
PC6353  1U_0402_6.3V6K  [C_0402]  227.8 92.55 90 top
PC6354  1U_0402_6.3V6K  [C_0402]  254.01 106.79 270 top
PC6355  1U_0402_6.3V6K  [C_0402]  247.35 106.14 0 top
PC6356  1U_0402_6.3V6K  [C_0402]  234.02 103.47 270 top
PC6357  1U_0402_6.3V6K  [C_0402]  253.95 118.07 90 top
PC6358  1U_0402_6.3V6K  [C_0402]  239.61 88.73 90 top
PC6359  22U_0805_6.3VAM  [C_0805]  247.11 114.84 180 top
PC6360  47U_0805_6.3V6M  [C_0805]  250.81 114.52 180 top
PC6361  10U_0603_6.3V6M  [C_0603]  237.52 91.03 180 top
PC6362  10U_0603_6.3V6M  [C_0603]  237.52 95.6 180 top
PC6363  470U_D2_2VM_R4.5M~D  [C_D1]  277.43 62.77 0 top
PC6364  1U_0402_6.3V6K  [C_0402]  240.94 94.28 270 top
PC6365  1U_0402_6.3V6K  [C_0402]  240.94 88.73 90 top
PC6366  1U_0402_6.3V6K  [C_0402]  254.9 106.79 270 top
PC6367  1U_0402_6.3V6K  [C_0402]  242.41 97.78 270 top
PC6368  1U_0402_6.3V6K  [C_0402]  242.34 94.28 270 top
PC6369  1U_0402_6.3V6K  [C_0402]  253.44 115.4 90 top
PC6370  22U_0805_6.3VAM  [C_0805]  249.29 112.3 180 top
PC6371  22U_0805_6.3VAM  [C_0805]  247.26 110.2 180 top
PC6372  22U_0805_6.3VAM  [C_0805]  248.84 110.2 0 top
PC6373  47U_0805_6.3V6M  [C_0805]  245.35 108.08 180 top
PC6374  4.7U_0603_6.3V6K  [C_0603]  276.68 65.82 0 top
PC6375  4.7U_0603_6.3V6K  [C_0603]  276.68 67.09 0 top
PC6376  10U_0603_6.3V6M  [C_0603]  237.52 100.36 180 top
PC6377  10U_0603_6.3V6M  [C_0603]  237.52 103.28 180 top
PC6378  47U_0805_6.3V6M  [C_0805]  288.97 70.2 0 bottom
PC6379  4.7U_0603_6.3V6K  [C_0603]  233.82 128.56 0 bottom
PC6380  4.7U_0603_6.3V6K  [C_0603]  256.8 121.51 180 bottom
PC6381  4.7U_0603_6.3V6K  [C_0603]  237.82 128.49 180 bottom
PC6382  4.7U_0603_6.3V6K  [C_0603]  262.25 126.21 0 bottom
PC6383  4.7U_0603_6.3V6K  [C_0603]  257.88 120.24 0 bottom
PC6384  4.7U_0603_6.3V6K  [C_0603]  262.25 125 0 bottom
PC6385  4.7U_0603_6.3V6K  [C_0603]  232.86 128.56 180 bottom
PC6386  4.7U_0603_6.3V6K  [C_0603]  228.85 128.56 0 bottom
PC6387  4.7U_0603_6.3V6K  [C_0603]  257.88 121.44 0 bottom
PC6388  470U_D2_2VM_R4.5M~D  [C_D1]  257.77 126.97 180 bottom
PC6389  470U_D2_2VM_R4.5M~D  [C_D1]  242.12 126.97 0 bottom
PC6390  470U_D2_2VM_R4.5M~D  [C_D1]  240.82 105.81 270 top
PC6391  470U_D2_2VM_R4.5M~D  [C_D1]  232.75 98.53 270 top
PC6392  10U_0603_6.3V6M  [C_0603]  262.2 121.06 180 bottom
PC6393  10U_0603_6.3V6M  [C_0603]  262.2 122.33 180 bottom
PC6394  10U_0603_6.3V6M  [C_0603]  262.26 128.68 0 bottom
PC6395  10U_0603_6.3V6M  [C_0603]  239.02 128.49 0 bottom
PC6396  10U_0603_6.3V6M  [C_0603]  262.2 119.86 180 bottom
PC6397  10U_0603_6.3V6M  [C_0603]  262.2 123.6 180 bottom
PC6398  10U_0603_6.3V6M  [C_0603]  262.26 127.48 0 bottom
PC6399  10U_0603_6.3V6M  [C_0603]  222.64 128.56 180 bottom
PC6400  10U_0603_6.3V6M  [C_0603]  256.85 122.78 180 bottom
PC6401  10U_0603_6.3V6M  [C_0603]  257.88 123.92 0 bottom
PC6402  10U_0603_6.3V6M  [C_0603]  257.88 122.71 0 bottom
PC6403  10U_0603_6.3V6M  [C_0603]  256.8 120.24 180 bottom
PC6404  10U_0603_6.3V6M  [C_0603]  256.85 123.98 180 bottom
PC6405  10U_0603_6.3V6M  [C_0603]  262.2 118.65 180 bottom
PC6406  10U_0603_6.3V6M  [C_0603]  223.78 128.56 0 bottom
PC6407  10U_0603_6.3V6M  [C_0603]  227.78 128.56 180 bottom
PC6408  10U_0603_6.3V6M  [C_0603]  237.52 106.27 180 top
PC6409  10U_0603_6.3V6M  [C_0603]  237.52 98.46 180 top
PC6410  10U_0603_6.3V6M  [C_0603]  237.52 94.14 180 top
PC6411  10U_0603_6.3V6M  [C_0603]  237.52 92.62 180 top
PC6412  10U_0603_6.3V6M  [C_0603]  237.52 97.06 180 top
PC6413  10U_0603_6.3V6M  [C_0603]  237.52 101.76 180 top
PC6414  10U_0603_6.3V6M  [C_0603]  237.52 104.68 180 top
PC6415  0.22U_0603_25V7K  [C_0603]  300.03 50.35 180 top
PC6416  4.7U_0603_6.3V  [C_0603]  303.4 48.46 270 top
PC6417  1U_0402_25V6K  [C_0402]  289.76 41.94 0 top
PC6418  1000P_0402_50V7K  [C_0402]  289.76 40.1 0 top
PC6419  0.1U_0402_25V6  [C_0402]  289.76 40.99 0 top
PC6420  2200P_0402_50V7K  [C_0402]  289.76 39.21 0 top
PC6421  10U_0805_25V6K~D  [C_0805]  289.7 43.26 0 top
PC6422  10U_0805_25V6K~D  [C_0805]  289.74 45.04 0 top
PC6423  0.22U_0603_25V7K  [C_0603]  306.02 49.75 0 top
PC6425  470U_D2_2VM_R4.5M~D  [C_D1]  287.82 66.85 0 bottom
PC6426  1000P_0402_25V8J  [C_0402]  297.88 55.92 0 top
PC6427  0.1U_0603_16V  [C_0603]  297.33 54.85 0 top
PC6428  3300P_0805_50V7K  [C_0805]  286.53 50.81 180 top
PC6429  1U_0402_25V6K  [C_0402]  285.95 41.5 180 top
PC6430  0.1U_0402_25V6  [C_0402]  285.95 40.6 180 top
PC6431  2200P_0402_50V7K  [C_0402]  285.96 42.44 180 top
PC6432  10U_0805_25V6K~D  [C_0805]  286.44 43.8 180 top
PC6433  33U_D2_25VM_R40M  [C_EEFCX1E330R]  277.03 36.08 180 bottom
PC6434  47P_0402_50V8J  [C_0402]  297.79 58.27 0 top
PC6435  1000P_0402_50V7K  [C_0402]  285.97 39.71 180 top
PC6436  10U_0805_25V6K~D  [C_0805]  286.47 45.58 180 top
PC6437  1500P_0402_50V7K  [C_0402]  304.1 57.36 90 top
PC6438  470U_D2_2VM_R4.5M~D  [C_D1]  286.5 62.75 0 top
PC6439  4700P_0402_50V7K  [C_0402]  305.9 59.13 180 top
PC6440  3300P_0805_50V7K  [C_0805]  277.9 51.04 270 top
PC6441  0.01U_0402_16V  [C_0402]  301.42 59.16 0 top
PC6442  22U_0603_6.3V6M  [C_0603]  276.68 66.77 0 bottom
PC6443  22U_0603_6.3V6M  [C_0603]  276.68 65.56 0 bottom
PC6444  22U_0603_6.3V6M  [C_0603]  279.22 65.82 0 top
PC6445  22U_0603_6.3V6M  [C_0603]  279.22 67.09 0 top
PC8200  2.2U_0603_16V6K  [C_0603]  247.97 34.45 0 bottom
PC8201  2200P_0402_50V7K  [C_0402]  260.35 23.34 0 bottom
PC8202  0.1U_0402_25V6  [C_0402]  257.2 23.21 180 bottom
PC8203  10U_0805_25V6K~D  [C_0805]  260.4 24.67 0 top
PC8204  10U_0805_25V6K~D  [C_0805]  257.02 24.54 180 top
PC8205  0.1U_0402_25V6  [C_0402]  240.53 34.51 0 bottom
PC8206  0.22U_0603_25V7K  [C_0603]  247.72 31.09 0 bottom
PC8207  220U_D2 SX_2VY_R9M  [C_D2]  268.61 40.32 270 bottom
PC8208  220U_D2 SX_2VY_R9M  [C_D2]  258.22 43.72 180 bottom
PC8210  680P_0402_50V7K  [C_0402]  265.69 29.83 270 top
PC8211  0.1U_0402_25V6  [C_0402]  244.12 29.88 180 bottom
PC8212  10U_0805_25V6K~D  [C_0805]  257.02 24.54 180 bottom
PC8213  0.22U_0603_25V7K  [C_0603]  247.65 35.91 90 bottom
PC8214  10U_0805_25V6K~D  [C_0805]  260.4 24.67 0 bottom
PC8215  0.1U_0402_25V6  [C_0402]  241.58 34.44 180 top
PC8216  47P_0402_50V8J  [C_0402]  243.21 36.4 90 bottom
PC8217  2200P_0402_50V7K  [C_0402]  241.58 31.77 180 top
PC8218  0.1U_0402_25V6  [C_0402]  244.24 36.92 180 top
PC8219  680P_0402_50V7K  [C_0402]  251.91 29.83 270 top
PC8220  1000P_0402_50V7K  [C_0402]  257.2 23.21 180 top
PC8221  1U_0402_25V6K  [C_0402]  260.35 23.34 0 top
PC8222  0.1U_0402_25V6  [C_0402]  238.25 29.75 0 bottom
PD1  SM24_SOT23  [TP0610K-T1-E3_SOT23-3]  321 49.23 180 top
PD2  -  [TVNST52302AB0_SOT523-3]  83.4 13.08 180 top
PD3  -  [TVNST52302AB0_SOT523-3]  79.22 7.59 180 top
PD5  -  [BAS40CW_SOT323-3]  294.18 42.39 180 top
PD100  -  [BAS40CW_SOT323-3]  60.51 45.24 90 top
PD101  -  [LL4148_LL34-2]  53.5 17.38 0 bottom
PD700  BAT54CW-7-F SOT-323  [BAT54CW_SOT323-3]  60.27 19.02 90 bottom
PH1  100K_0402_1%_B25/50 4250K  [R_0402]  153.29 110.42 270 top
PH500  470K_0402_5%_B25/50 4700K  [R_0402]  139.68 148.13 90 bottom
PH501  10K +-5% 0402 B25/50 4250K  [R_0402]  187.51 133.2 180 bottom
PH502  10K +-5% 0402 B25/50 4250K  [R_0402]  121.8 147.81 180 top
PH503  10K +-5% 0402 B25/50 4250K  [R_0402]  163.38 129.13 0 bottom
PH504  470K_0402_5%_B25/50 4700K  [R_0402]  163.06 146.78 0 bottom
PH6000  470K_0402_5%_B25/50 4700K  [R_0402]  251.23 145 180 bottom
PJ800  -  [JUMP_43X39]  247.61 39.97 180 bottom
PJP100  -  [JUMP_43X118]  44.97 43.58 90 top
PJP101  -  [JUMP_43X118]  38.49 42.96 90 top
PJP102  -  [JUMP_43X118]  45.6 20.18 90 top
PJP104  -  [JUMP_43X118]  40.33 20.18 90 top
PJP200  -  [JUMP_43X118]  97.23 30.26 0 top
PJP201  -  [JUMP_43X118]  97.23 24.92 0 top
PJP202  -  [JUMP_43X39]  93.1 50.07 90 bottom
PJP203  -  [JUMP_43X39]  89.06 31.53 90 top
PJP300  -  [JUMP_43X118]  247.4 26.15 90 bottom
PJP301  -  [JUMP_43X39]  259.28 14.78 270 top
PJP302  -  [JUMP_43X118]  242.2 26.15 90 bottom
PJP504  -  [JUMP_43X39]  118.31 121.33 270 bottom
PJP505  -  [JUMP_43X118]  123.7 101.8 270 bottom
PJP801  -  [JUMP_43X79]  234.13 45.96 90 bottom
PJP802  -  [JUMP_43X39]  233.83 35.85 180 bottom
PJP803  -  [JUMP_43X79]  220.99 45.08 90 bottom
PJP1300  -  [JUMP_43X79]  102.78 40.61 0 bottom
PJP1301  -  [JUMP_43X79]  101.62 54.96 270 bottom
PJP8200  -  [JUMP_43X39]  260.66 21.75 0 bottom
PJP8201  -  [JUMP_43X118]  263.33 44.79 90 bottom
PJP8202  -  [JUMP_43X118]  268.61 44.82 90 bottom
PJPDC1  ACES_50290-01301-P01  [ACES_50290-01301-P01_13P-T]  66.32 44.1 0 bottom
PL1  SMB3025500YA_2P  [CHENG_SMB3025500YA_2P]  81.86 33.75 180 bottom
PL2  BLM15HG601SN1D_2P  [MURAT_BLM15HG601SN1D_2P]  29.09 40.49 90 bottom
PL3  SMB3025500YA_2P  [CHENG_SMB3025500YA_2P]  81.86 37.27 180 bottom
PL4  SMB3025500YA_2P  [CHENG_SMB3025500YA_2P]  83.38 24.42 270 bottom
PL5  SMB3025500YA_2P  [CHENG_SMB3025500YA_2P]  87.13 24.42 270 bottom
PL100  1UH_6.6A_20%_5X5X3_M  [L_5X5X3_M_2P]  53.41 33.05 90 bottom
PL101  2.2UH_PCMB104T-2R2MS_12A_20%  [CYNTE_PCMB104T-2R2MS_2P]  49.54 19.12 90 bottom
PL102  2.2UH_PCMB104T-2R2MS_12A_20%  [CYNTE_PCMB104T-2R2MS_2P]  45.22 33.91 90 bottom
PL201  1UH_11A_20%_7X7X3_M  [L_7X7X3_M_2P]  97.15 35 180 bottom
PL300  1UH_11A_20%_7X7X3_M  [L_7X7X3_M_2P]  255 19.46 180 bottom
PL500  FBMA-L11-453215800LMA90T_2P  [KC_FBMA-L11-453215800LMA90T_2P]  137.17 142.09 90 bottom
PL501  0.15UH_PCME064T-R15MS0R667_36A_20%  [CYNTE_PCME064T-R15MS0R667_2P]  161.87 135.57 180 bottom
PL502  0.15UH_PCME064T-R15MS0R667_36A_20%  [CYNTE_PCME064T-R15MS0R667_2P]  165.5 135.44 0 bottom
PL503  0.15UH_PCME064T-R15MS0R667_36A_20%  [CYNTE_PCME064T-R15MS0R667_2P]  177.02 131.41 90 bottom
PL505  0.15UH_PCME064T-R15MS0R667_36A_20%  [CYNTE_PCME064T-R15MS0R667_2P]  143.57 134.65 90 bottom
PL506  0.15UH_PCME064T-R15MS0R667_36A_20%  [CYNTE_PCME064T-R15MS0R667_2P]  150.69 134.66 90 bottom
PL508  0.47UH_PCMB053T-R47MS_12A_20%  [CYNTE_PCMB053T-R47MS_2P]  183.57 136.25 270 bottom
PL509  1UH_PCMB042T-1R0MS_4.5A_20%  [CYNTE_PCMB042T-1R0MS_2P]  126.18 111.42 270 bottom
PL700  2.2UH_PCMB104T-2R2MS_12A_20%  [CYNTE_PCMB104T-2R2MS_2P]  65.72 23.91 0 bottom
PL701  1UH_6.6A_20%_5X5X3_M  [L_5X5X3_M_2P]  56.57 29.12 0 bottom
PL800  1UH_PCMB042T-1R0MS_4.5A_20%  [CYNTE_PCMB042T-1R0MS_2P]  245.79 45.7 180 bottom
PL801  1UH_PCMB042T-1R0MS_4.5A_20%  [CYNTE_PCMB042T-1R0MS_2P]  230.38 46.97 180 bottom
PL6100  0.22UH_MMD12DZNR22MEX_40A_20%  [MAG_MMD12DZNR22MEX_4P]  257.25 143.1 270 bottom
PL6101  0.22UH_MMD12DZNR22MEX_40A_20%  [MAG_MMD12DZNR22MEX_4P]  243.47 143.04 270 bottom
PL6200  0.22UH_MMD12DZNR22MEX_40A_20%  [MAG_MMD12DZNR22MEX_4P]  229.75 142.98 270 bottom
PL6201  0.22UH_MMD12DZNR22MEX_40A_20%  [MAG_MMD12DZNR22MEX_4P]  216.1 142.98 270 bottom
PL6400  0.22UH_MMD-10DZ-R22MES1L_35A_20%  [MAG_MMD-10DZ-R22MES1L_2P]  290.24 52.67 90 bottom
PL6401  0.22UH_MMD-10DZ-R22MES1L_35A_20%  [MAG_MMD-10DZ-R22MES1L_2P]  279.64 52.43 90 bottom
PL8200  S COIL 0.47UH +-20% PCMB063T-R47MS 18A  [L_7X7X3_M_2P]  262.14 33.2 90 bottom
PL8201  S COIL 0.47UH +-20% PCMB063T-R47MS 18A  [L_7X7X3_M_2P]  254.39 33.26 90 bottom
PQ2  S TR METR3904W-G NPN SOT323-3  [RHU002N06_SOT323-3]  316.09 51.24 270 top
PQ3  -  [SI3457CDV-T1-GE3_TSOP6]  68.54 10.89 0 top
PQ4  L2N7002WT1G 1N SC-70-3  [SSM3K7002FU_SC70-3]  70.56 9.3 180 top
PQ7  FDV301N_G 1N SOT23-3  [FDV301N_NL_SOT23-3]  316.44 47.86 90 top
PQ8  L2N7002WT1G 1N SC-70-3  [SSM3K7002FU_SC70-3]  74.24 8.16 270 top
PQ100  -  [AON7518_DFN8-5]  50.68 29.05 0 top
PQ101  -  [AON7534_DFN3X3-8-5]  48.78 31.59 180 top
PQ102  -  [AON7518_DFN8-5]  44.55 36.99 0 top
PQ103  -  [AON7534_DFN3X3-8-5]  47.38 33.48 90 top
PQ200  -  [AON7408L_DFN8-5]  91.91 38.45 180 top
PQ201  -  [AON7506_DFN33-8-5]  93.73 35.4 0 top
PQ202  S TR 2N7002KDW 2N SOT-363-6  [2N7002DW-7-F_SOT363-6]  104.99 54.68 270 top
PQ300  -  [AON7408L_DFN8-5]  254.1 21.72 270 top
PQ301  -  [AON7506_DFN33-8-5]  256.97 16.06 90 top
PQ700  L2N7002WT1G 1N SC-70-3  [SSM3K7002FU_SC70-3]  66.3 31.53 270 bottom
PQ701  -  [MDU1512RH_POWERDFN56-8-5]  69.76 38.83 270 top
PQ702  -  [MDU1512RH_POWERDFN56-8-5]  67.49 37.98 270 bottom
PQ703  -  [MDU1512RH_POWERDFN56-8-5]  81.57 31.85 270 top
PQ704  -  [AON6414AL_DFN8-5]  69.67 19.59 0 top
PQ705  L2N7002WT1G 1N SC-70-3  [SSM3K7002FU_SC70-3]  63.21 18.76 90 top
PQ706  AON7518 1N DFN  [MDV1525URH_PDFN33-8-5]  65.03 23.59 270 top
PQ707  -  [MDU1512RH_POWERDFN56-8-5]  69.73 34.2 90 bottom
PQ708  -  [MDU1512RH_POWERDFN56-8-5]  67.08 35.1 90 top
PQ710  S TR 2N7002KDW 2N SOT-363-6  [2N7002DW-7-F_SOT363-6]  119.73 78.55 270 top
PQ6400  -  [AON6992_DFN5X6D-8-7]  289.08 45 90 bottom
PQ6401  -  [AON6992_DFN5X6D-8-7]  289.01 39.24 90 bottom
PQ6402  -  [AON6992_DFN5X6D-8-7]  287.14 43.02 270 bottom
PQ6403  -  [AON6992_DFN5X6D-8-7]  287.08 48.76 270 bottom
PQ8200  AON6992 2N DFN5X6D  [FDMS3660S_POWER56-8-7]  259.87 26.45 90 bottom
PQ8201  AON6992 2N DFN5X6D  [FDMS3660S_POWER56-8-7]  257.54 30.13 270 bottom
PQ8202  DMN53D0LDW-7 2N SOT363-6  [2N7002DW-7-F_SOT363-6]  239.1 30.73 180 bottom
PQ8203  DMN53D0LDW-7 2N SOT363-6  [2N7002DW-7-F_SOT363-6]  276.99 150.53 270 top
PR2  1K_0402_1%  [R_0402]  293.95 39.66 0 top
PR3  2.2K_0402_5%  [R_0402]  312.56 48.53 90 top
PR4  33_0402_5%  [R_0402]  312.56 46.76 90 top
PR6  100K_0402_1%  [R_0402]  318.3 47.66 270 top
PR8  10K_0402_1%  [R_0402]  314.78 51.48 270 top
PR9  15K_0402_1%  [R_0402]  318.3 49.44 270 top
PR12  100K_0402_1%  [R_0402]  73.81 10.45 180 top
PR13  100K_0402_1%  [R_0402]  71.7 10.43 90 top
PR14  100K_0402_1%  [R_0402]  67.95 8.17 270 top
PR16  10K_0402_1%  [R_0402]  81.87 8.91 180 top
PR17  0_0402_5%  [R0402_0OHM]  68.86 9.05 180 top
PR19  100_0402_1%  [R_0402]  82.48 11.82 90 top
PR21  100_0402_1%  [R_0402]  81.59 11.82 90 top
PR22  100_0402_1%  [R_0402]  79.79 10.83 270 top
PR23  110K_0402_1%  [R_0402]  292.26 5.4 90 top
PR24  14.7K_0402_1%  [R_0402]  312.71 51.48 270 top
PR25  12.1K_0402_1%  [R_0402]  313.64 51.48 270 top
PR26  100K_0402_1%  [R_0402]  294.14 6.32 270 top
PR28  100K_0402_1%  [R_0402]  77.37 8.73 270 top
PR100  0_0402_5%  [R0402_0OHM]  59.65 47.88 270 top
PR101  6.49K_0402_1%  [R_0402]  57.12 49.47 180 bottom
PR102  15K_0402_1%  [R_0402]  50.88 49.42 180 bottom
PR103  10K_0402_1%  [R_0402]  55.19 49.45 270 bottom
PR104  10K_0402_1%  [R_0402]  52.02 48.53 90 bottom
PR105  113K_0402_1%  [R_0402]  57.11 48.6 180 bottom
PR106  84.5K_0402_1%  [R_0402]  49.97 48.53 0 bottom
PR107  200_0402_1%  [R_0402]  50.12 46.5 180 bottom
PR108  0_0603_5%  [R_0603]  58.62 44.61 180 bottom
PR109  0_0603_5%  [R_0603]  50.74 44.53 180 bottom
PR110  4.7_1206_5%  [R_1206]  44.49 26.86 90 top
PR111  4.7_1206_5%  [R_1206]  42.62 35.04 270 top
PR112  0_0402_5%  [R0402_0OHM]  60.57 47.88 270 top
PR113  2.2K_0402_5%  [R_0402]  61.91 44.35 90 top
PR114  0_0402_5%  [R0402_0OHM]  58.77 47.88 270 top
PR115  1M_0402_1%  [R_0402]  62.79 44.35 90 top
PR116  200K_0402_1%  [R_0402]  62.15 46.14 0 top
PR200  2.2_0603_5%  [R_0603]  88.21 43.78 0 bottom
PR201  24.3K_0402_1%  [R_0402]  97.35 40.8 270 bottom
PR202  4.7_1206_5%  [R_1206]  97.61 38.26 270 top
PR203  5.1_0603_5%  [R_0603]  96.21 39.4 90 bottom
PR204  2.2_0603_5%  [R_0603]  92.27 39.4 90 bottom
PR205  12K_0402_1%  [R_0402]  95.02 48.04 180 bottom
PR206  887K_0402_1%  [R_0402]  96.71 42.69 180 bottom
PR207  20K_0402_1%  [R_0402]  95.02 47.15 180 bottom
PR208  0_0402_5%  [R0402_0OHM]  96.8 43.59 180 bottom
PR209  0_0402_5%  [R_0402]  95.88 46.39 0 bottom
PR210  100K_0402_1%  [R_0402]  96.71 41.79 180 bottom
PR211  0_0402_5%  [R0402_0OHM]  95.88 47.34 0 bottom
PR212  1K_0402_1%  [R_0402]  102.28 50.98 90 top
PR213  60.4K_0402_1%  [R_0402]  101.39 50.98 90 top
PR214  1K_0402_1%  [R_0402]  106.17 51.38 90 top
PR215  60.4K_0402_1%  [R_0402]  104.99 51.38 90 top
PR300  0_0402_5%  [R0402_0OHM]  240.92 16.92 0 top
PR301  100K_0402_1%  [R_0402]  244.12 20.8 180 top
PR302  2.2_0603_5%  [R_0603]  246.58 20.8 0 top
PR303  200K_0402_1%  [R_0402]  241.63 19.35 270 top
PR305  4.7_1206_5%  [R_1206]  257.95 21.18 270 bottom
PR306  470K_0402_1%  [R_0402]  243.2 14.89 0 top
PR307  4.42K_0402_1%  [R_0402]  241.83 14.26 180 top
PR308  10K_0402_1%  [R_0402]  241.83 15.15 180 top
PR500  97.6K_0402_1%  [R_0402]  125.55 138.67 270 top
PR501  45.3_0402_1%  [R_0402]  124.94 132.87 90 top
PR502  75_0402_1%  [R_0402]  125.83 132.87 90 top
PR503  100_0402_1%  [R_0402]  126.72 132.87 90 top
PR504  0_0402_5%  [R0402_0OHM]  124.06 135.23 90 bottom
PR505  1_0402_5%  [R_0402]  126.73 135.29 90 top
PR506  0_0402_5%  [R0402_0OHM]  127.6 136.19 0 top
PR507  0_0402_5%  [R0402_0OHM]  124.95 132.88 90 bottom
PR508  49.9_0402_1%  [R_0402]  124.95 135.23 90 bottom
PR509  0_0402_5%  [R0402_0OHM]  125.84 133.79 270 bottom
PR510  0_0402_5%  [R0402_0OHM]  125.84 135.23 90 bottom
PR511  0_0402_5%  [R0402_0OHM]  126.73 133.79 270 bottom
PR512  10_0402_1%  [R_0402]  126.73 135.23 90 bottom
PR513  27.4K_0402_1%  [R_0402]  119.54 135.24 0 bottom
PR514  12.4K_0402_1%  [R_0402]  120.43 136.13 0 bottom
PR515  1.91K_0402_1%  [R_0402]  122.56 135.21 90 top
PR516  16.9K_0402_1%  [R_0402]  129.39 136.2 270 bottom
PR517  28K_0402_1%  [R_0402]  128.5 136.2 270 bottom
PR518  110K_0402_1%  [R_0402]  127.62 136.2 270 bottom
PR519  169K_0402_1%  [R_0402]  130.28 136.2 270 bottom
PR520  0_0402_5%  [R0402_0OHM]  123.45 135.21 90 top
PR521  3.6K_0402_1%  [R_0402]  121.17 140.51 270 top
PR522  2K_0402_1%  [R_0402]  119.49 138.93 270 bottom
PR523  0_0402_5%  [R0402_0OHM]  123.17 135.23 90 bottom
PR524  1.27K_0402_1%  [R_0402]  132.17 139.37 0 bottom
PR525  1K_0402_1%  [R_0402]  120.38 138.02 90 bottom
PR526  0_0402_5%  [R0402_0OHM]  122.28 135.23 90 bottom
PR527  48.7K_0402_1%  [R_0402]  129.74 137.26 180 top
PR528  1K_0402_1%  [R_0402]  133.1 138.48 270 bottom
PR529  11K_0402_1%  [R_0402]  133.09 142.01 180 bottom
PR530  3.6K_0402_1%  [R_0402]  186.59 134.09 0 bottom
PR531  2.94K_0402_1%  [R_0402]  121.33 139.19 270 bottom
PR532  316_0402_1%  [R_0402]  132.17 143.85 0 bottom
PR533  2.74K_0402_1%  [R_0402]  132.17 142.92 0 bottom
PR534  2.61K_0402_1%  [R_0402]  123.58 147.81 180 top
PR535  11K_0402_1%  [R_0402]  120.39 139.87 180 bottom
PR536  2K_0402_1%  [R_0402]  132.17 144.76 0 bottom
PR537  4.53K_0402_1%  [R_0402]  129.74 142.22 270 top
PR538  1K_0402_1%  [R_0402]  120.49 144.51 0 bottom
PR539  110K_0402_1%  [R_0402]  128.79 143.66 90 top
PR540  294_0402_1%  [R_0402]  120.5 143.63 270 bottom
PR541  383_0402_1%  [R_0402]  127.29 146.03 0 bottom
PR542  11K_0402_1%  [R_0402]  124.38 146.94 270 top
PR543  1K_0402_1%  [R_0402]  129.08 146.94 270 bottom
PR544  4.42K_0402_1%  [R_0402]  123.49 146.94 270 top
PR545  12.4K_0402_1%  [R_0402]  123.41 146.03 0 bottom
PR546  1K_0402_1%  [R_0402]  125.27 146.02 90 bottom
PR547  27.4K_0402_1%  [R_0402]  122.54 146.94 270 bottom
PR548  93.1K_0402_1%  [R_0402]  122.98 143.76 270 top
PR549  2K_0402_1%  [R_0402]  124.38 146.91 90 bottom
PR550  3.57K_0402_1%  [R_0402]  126.15 146.94 270 bottom
PR551  4.87K_0402_1%  [R_0402]  125.02 144.31 0 top
PR552  0_0402_5%  [R0402_0OHM]  157.38 147.58 270 bottom
PR553  1_0402_5%  [R_0402]  159.16 146.66 90 bottom
PR554  4.7_0603_1%  [R_0603]  161.68 147.72 270 bottom
PR555  10_1206_5%  [R_1206]  157.74 137.89 0 top
PR556  0_0402_5%  [R0402_0OHM]  158.27 147.58 270 bottom
PR557  3.65K_0603_1%  [R_0603]  158.73 136.26 0 top
PR558  100K_0402_1%  [R_0402]  159.58 135.05 180 top
PR559  10_0402_1%  [R_0402]  159.61 133.25 90 top
PR560  100K_0402_1%  [R_0402]  158.69 133.24 90 top
PR561  100K_0402_1%  [R_0402]  157.77 133.25 90 top
PR562  20M_0402_5%  [R_0402]  157.74 136.45 270 top
PR563  0_0402_5%  [R0402_0OHM]  165.93 147.27 270 bottom
PR564  4.7_0603_1%  [R_0603]  170.01 147.64 270 bottom
PR565  10_1206_5%  [R_1206]  167.2 137.83 0 top
PR566  0_0402_5%  [R0402_0OHM]  166.82 147.27 270 bottom
PR567  3.65K_0603_1%  [R_0603]  167.07 136.24 0 top
PR568  100K_0402_1%  [R_0402]  168 135.18 180 top
PR569  10_0402_1%  [R_0402]  168.03 133.37 90 top
PR570  100K_0402_1%  [R_0402]  166.18 133.37 90 top
PR571  100K_0402_1%  [R_0402]  167.07 133.37 90 top
PR572  20M_0402_5%  [R_0402]  141.42 140.19 270 top
PR573  0_0402_5%  [R0402_0OHM]  174.25 147.3 270 bottom
